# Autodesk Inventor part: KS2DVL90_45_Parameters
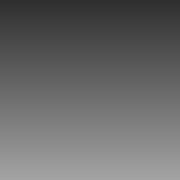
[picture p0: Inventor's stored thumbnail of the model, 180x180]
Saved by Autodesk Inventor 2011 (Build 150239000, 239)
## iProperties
Created: 2010-10
Document SubType Name: Modeling
Designer: TB
Density: 1 g/cm^3
Slaglengde: 100,000 mm
Vinkel_Minusport: 0.00 deg
Forlengelse_rør: 0.000 mm
Minusport2: 180.00 deg
Author: TB
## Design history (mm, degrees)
other parameters: "Slaglengde" = 100 [user parameter], "Forlengelse_rør" = 0 [user parameter], "Vinkel_Minusport" = 0 deg [user parameter], "Minusport2" = 180 deg [user parameter]
